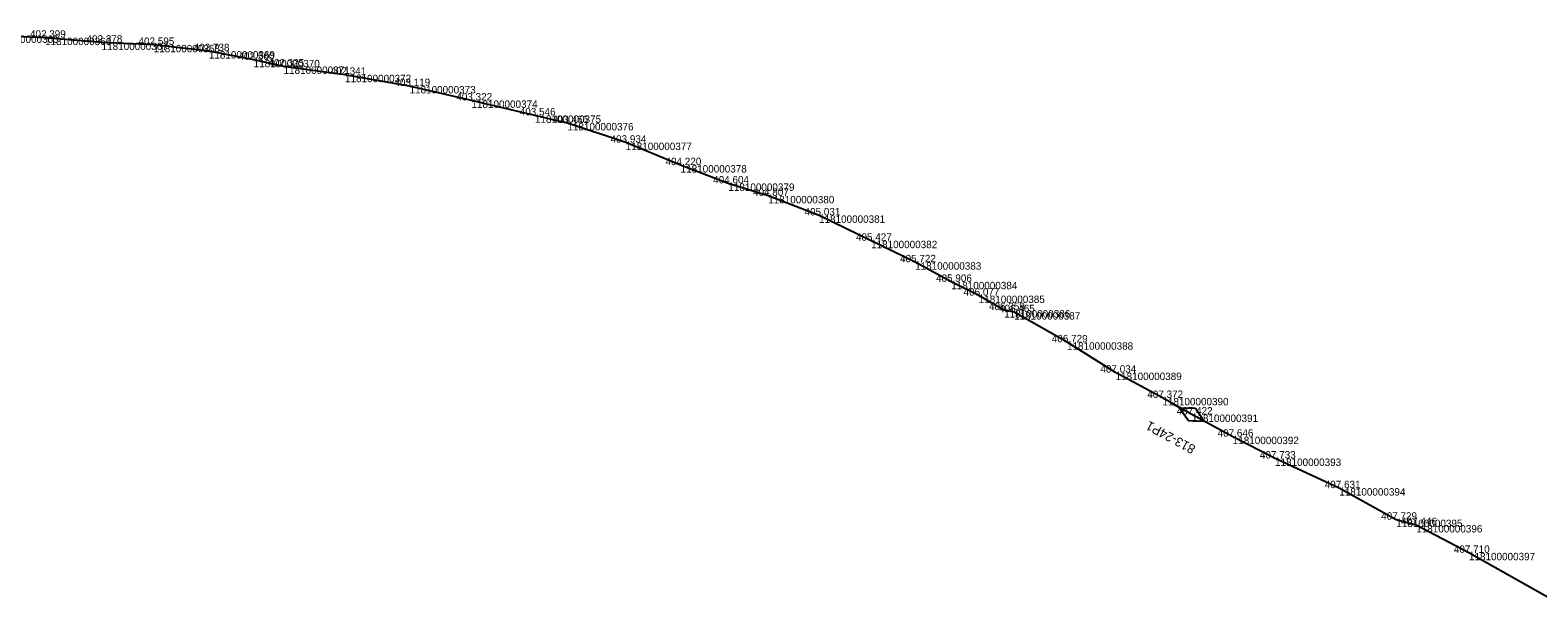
# Model space of a CAD drawing. Extents: x -724084 to -720954, y -948423 to -945131.
# Drawn here: x -723241.5 to -722997.3, y -945430.6 to -945338 of the extents above; entities that cross this region are included whole.
import ezdxf

# ---------------------------------------------------------------- set-up
doc = ezdxf.new("R2010")
doc.units = 0
for name, color, linetype in [('Vrstva 28', 7, 'Continuous'), ('Vrstva 31', 7, 'Continuous'), ('Vrstva 33', 7, 'Continuous'), ('Vrstva 60', 7, 'Continuous'), ('Vrstva 61', 7, 'Continuous')]:
    doc.layers.add(name, color=color, linetype=linetype)

msp = doc.modelspace()

# ---------------------------------------------------------------- linework, layer by layer
at = {"layer": 'Vrstva 28'}
for p, q in [((-723050.3, -945401.92), (-723056.44, -945398.59)), ((-723053.93, -945401.28), (-723055.42, -945399.15)), ((-723055.42, -945399.15), (-723052.81, -945399.23)), ((-723052.81, -945399.23), (-723051.32, -945401.37)), ((-723051.32, -945401.37), (-723053.93, -945401.28))]:
    msp.add_line(p, q, dxfattribs=at)
msp.add_lwpolyline([(-722994.41, -945430.58), (-723008.5, -945422.65), (-723017.04, -945418.15), (-723020.27, -945417.28), (-723029.5, -945412.18), (-723039.91, -945407.38), (-723046.76, -945403.85), (-723053.37, -945400.26), (-723058.15, -945397.57), (-723065.73, -945393.48), (-723073.6, -945388.57), (-723082.16, -945383.69), (-723083.78, -945383.35), (-723087.9, -945381.01), (-723092.35, -945378.78), (-723098.19, -945375.61), (-723105.33, -945372.13), (-723113.76, -945368.03), (-723121.99, -945364.86), (-723128.45, -945362.85), (-723136.17, -945359.89), (-723145.07, -945356.25), (-723154.51, -945353.07), (-723159.77, -945351.84), (-723170.05, -945349.42), (-723180.08, -945347.08), (-723190.53, -945345.26), (-723200.48, -945343.92), (-723205.32, -945342.85), (-723212.58, -945341.44), (-723221.51, -945340.42), (-723229.94, -945340.06), (-723239.1, -945339.26), (-723247.62, -945338.9)], dxfattribs=at)
at = {"layer": 'Vrstva 31'}
msp.add_lwpolyline([(-722994.41, -945430.58), (-723008.5, -945422.65), (-723017.04, -945418.15), (-723020.27, -945417.28), (-723029.5, -945412.18), (-723039.91, -945407.38), (-723046.76, -945403.85), (-723053.37, -945400.26), (-723058.15, -945397.57), (-723065.73, -945393.48), (-723073.6, -945388.57), (-723082.16, -945383.69), (-723083.78, -945383.35), (-723087.9, -945381.01), (-723092.35, -945378.78), (-723098.19, -945375.61), (-723105.33, -945372.13), (-723113.76, -945368.03), (-723121.99, -945364.86), (-723128.45, -945362.85), (-723136.17, -945359.89), (-723145.07, -945356.25), (-723154.51, -945353.07), (-723159.77, -945351.84), (-723170.05, -945349.42), (-723180.08, -945347.08), (-723190.53, -945345.26), (-723200.48, -945343.92), (-723205.32, -945342.85), (-723212.58, -945341.44), (-723221.51, -945340.42), (-723229.94, -945340.06), (-723239.1, -945339.26), (-723247.62, -945338.9)], dxfattribs=at)
at = {"layer": 'Vrstva 33'}
msp.add_lwpolyline([(-722994.41, -945430.58), (-723008.5, -945422.65), (-723017.04, -945418.15), (-723020.27, -945417.28), (-723029.5, -945412.18), (-723039.91, -945407.38), (-723046.76, -945403.85), (-723053.37, -945400.26), (-723058.15, -945397.57), (-723065.73, -945393.48), (-723073.6, -945388.57), (-723082.16, -945383.69), (-723083.78, -945383.35), (-723087.9, -945381.01), (-723092.35, -945378.78), (-723098.19, -945375.61), (-723105.33, -945372.13), (-723113.76, -945368.03), (-723121.99, -945364.86), (-723128.45, -945362.85), (-723136.17, -945359.89), (-723145.07, -945356.25), (-723154.51, -945353.07), (-723159.77, -945351.84), (-723170.05, -945349.42), (-723180.08, -945347.08), (-723190.53, -945345.26), (-723200.48, -945343.92), (-723205.32, -945342.85), (-723212.58, -945341.44), (-723221.51, -945340.42), (-723229.94, -945340.06), (-723239.1, -945339.26), (-723247.62, -945338.9)], dxfattribs=at)
at = {"layer": 'Vrstva 60'}
for p, q in [((-723239.1, -945339.26), (-723239.1, -945339.26)), ((-723229.94, -945340.06), (-723229.94, -945340.06)), ((-723221.51, -945340.42), (-723221.51, -945340.42)), ((-723212.58, -945341.44), (-723212.58, -945341.44)), ((-723205.32, -945342.85), (-723205.32, -945342.85)), ((-723200.48, -945343.92), (-723200.48, -945343.92)), ((-723190.53, -945345.26), (-723190.53, -945345.26)), ((-723180.08, -945347.08), (-723180.08, -945347.08)), ((-723170.05, -945349.42), (-723170.05, -945349.42)), ((-723159.77, -945351.84), (-723159.77, -945351.84)), ((-723154.51, -945353.07), (-723154.51, -945353.07)), ((-723145.07, -945356.25), (-723145.07, -945356.25)), ((-723136.17, -945359.89), (-723136.17, -945359.89)), ((-723128.45, -945362.85), (-723128.45, -945362.85)), ((-723121.99, -945364.86), (-723121.99, -945364.86)), ((-723113.76, -945368.03), (-723113.76, -945368.03)), ((-723105.33, -945372.13), (-723105.33, -945372.13)), ((-723098.19, -945375.61), (-723098.19, -945375.61)), ((-723092.35, -945378.78), (-723092.35, -945378.78)), ((-723087.9, -945381.01), (-723087.9, -945381.01)), ((-723083.78, -945383.35), (-723083.78, -945383.35)), ((-723082.16, -945383.69), (-723082.16, -945383.69)), ((-723073.6, -945388.57), (-723073.6, -945388.57)), ((-723065.73, -945393.48), (-723065.73, -945393.48)), ((-723058.15, -945397.57), (-723058.15, -945397.57)), ((-723053.37, -945400.26), (-723053.37, -945400.26)), ((-723046.76, -945403.85), (-723046.76, -945403.85)), ((-723039.91, -945407.38), (-723039.91, -945407.38)), ((-723029.5, -945412.18), (-723029.5, -945412.18)), ((-723020.27, -945417.28), (-723020.27, -945417.28)), ((-723017.04, -945418.15), (-723017.04, -945418.15)), ((-723008.5, -945422.65), (-723008.5, -945422.65))]:
    msp.add_line(p, q, dxfattribs=at)

# ---------------------------------------------------------------- texts
at = {"layer": 'Vrstva 28'}
msp.add_text('813-24P1', height=1.5, rotation=151.5002, dxfattribs=at).set_placement((-723052.65, -945405.4))
at = {"layer": 'Vrstva 60'}
for s, p in [('118100000365', (-723247.62, -945340.1)), ('118100000366', (-723239.1, -945340.46)), ('118100000367', (-723229.94, -945341.26)), ('118100000368', (-723221.51, -945341.62)), ('118100000369', (-723212.58, -945342.64)), ('118100000370', (-723205.32, -945344.05)), ('118100000371', (-723200.48, -945345.12)), ('118100000372', (-723190.53, -945346.46)), ('118100000373', (-723180.08, -945348.28)), ('118100000374', (-723170.05, -945350.62)), ('118100000375', (-723159.77, -945353.04)), ('118100000376', (-723154.51, -945354.27)), ('118100000377', (-723145.07, -945357.45)), ('118100000378', (-723136.17, -945361.09)), ('118100000379', (-723128.45, -945364.05)), ('118100000380', (-723121.99, -945366.07)), ('118100000381', (-723113.76, -945369.23)), ('118100000382', (-723105.33, -945373.33)), ('118100000383', (-723098.19, -945376.81)), ('118100000384', (-723092.35, -945379.98)), ('118100000385', (-723087.9, -945382.21)), ('118100000386', (-723083.78, -945384.56)), ('118100000387', (-723082.16, -945384.89)), ('118100000388', (-723073.6, -945389.77)), ('118100000389', (-723065.73, -945394.68)), ('118100000390', (-723058.15, -945398.77)), ('118100000391', (-723053.37, -945401.46)), ('118100000392', (-723046.76, -945405.05)), ('118100000393', (-723039.91, -945408.58)), ('118100000394', (-723029.5, -945413.38)), ('118100000395', (-723020.27, -945418.48)), ('118100000396', (-723017.04, -945419.35)), ('118100000397', (-723008.5, -945423.85))]:
    msp.add_text(s, height=1.2, dxfattribs=at).set_placement(p)
at = {"layer": 'Vrstva 61'}
for s, p in [('402.399', (-723241.55, -945339.26)), ('402.378', (-723232.39, -945340.06)), ('402.595', (-723223.97, -945340.42)), ('402.738', (-723215.04, -945341.44)), ('402.560', (-723207.77, -945342.85)), ('402.325', (-723202.94, -945343.92)), ('402.341', (-723192.89, -945345.26)), ('403.119', (-723182.53, -945347.08)), ('403.322', (-723172.5, -945349.42)), ('403.546', (-723162.23, -945351.84)), ('403.466', (-723156.96, -945353.07)), ('403.934', (-723147.52, -945356.25)), ('404.220', (-723138.62, -945359.89)), ('404.604', (-723130.9, -945362.85)), ('404.807', (-723124.45, -945364.86)), ('405.031', (-723116.11, -945368.03)), ('405.427', (-723107.78, -945372.13)), ('405.722', (-723100.64, -945375.61)), ('405.906', (-723094.81, -945378.78)), ('406.077', (-723090.35, -945381.01)), ('406.359', (-723086.23, -945383.35)), ('406.465', (-723084.61, -945383.69)), ('406.729', (-723076.06, -945388.57)), ('407.034', (-723068.19, -945393.48)), ('407.372', (-723060.6, -945397.57)), ('407.422', (-723055.82, -945400.26)), ('407.646', (-723049.21, -945403.85)), ('407.733', (-723042.36, -945407.38)), ('407.631', (-723031.86, -945412.18)), ('407.729', (-723022.72, -945417.28)), ('407.446', (-723019.49, -945418.15)), ('407.710', (-723010.95, -945422.65))]:
    msp.add_text(s, height=1.2, dxfattribs=at).set_placement(p)

doc.saveas('drawing.dxf')
